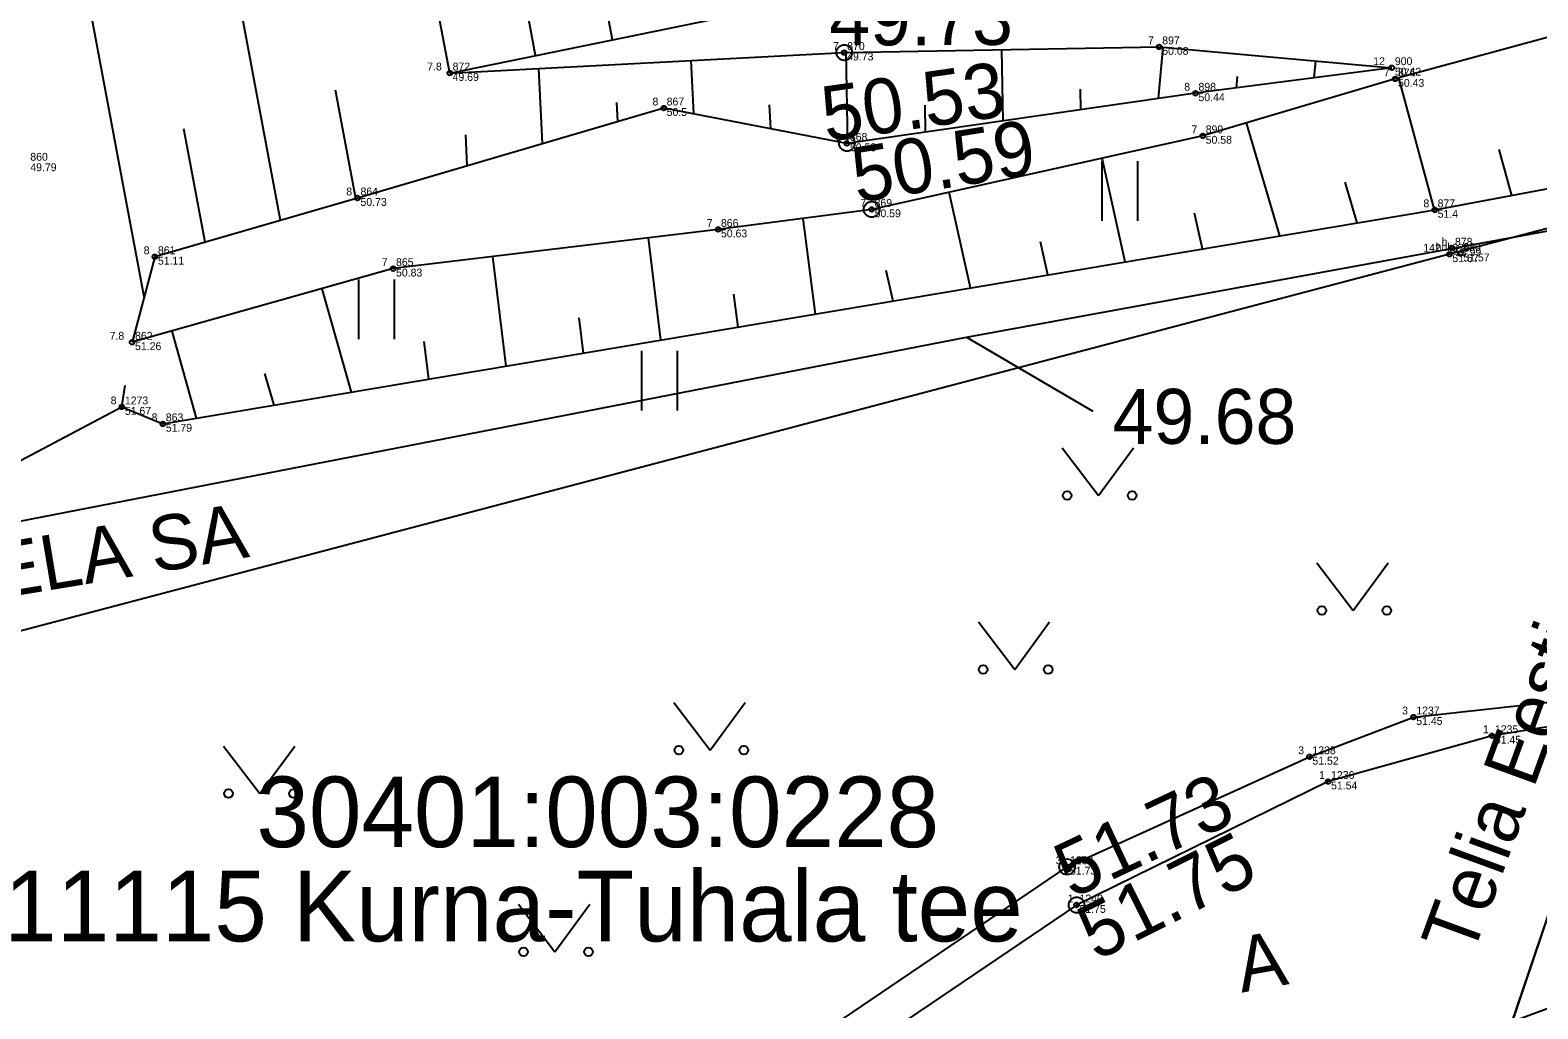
# Model space of a CAD drawing. Extents: x 543497 to 552146, y 6567125 to 6579845.
# Drawn here: x 546549.56 to 546568.77, y 6577762.04 to 6577774.51 of the extents above; entities that cross this region are included whole.
import ezdxf

# ---------------------------------------------------------------- set-up
doc = ezdxf.new("R2010")
doc.units = 0
for name, color, linetype in [('xref_Kangru tee 1_geodeesia$0$ABIJOONIS', 7, 'Continuous'), ('xref_Kangru tee 1_geodeesia$0$AED', 7, 'Continuous'), ('xref_Kangru tee 1_geodeesia$0$HALJASTUS', 7, 'Continuous'), ('xref_Kangru tee 1_geodeesia$0$korgus-EH2000', 7, 'Continuous'), ('xref_Kangru tee 1_geodeesia$0$mootkood', 7, 'Continuous'), ('xref_Kangru tee 1_geodeesia$0$MOOTKORG-eh2000', 7, 'Continuous'), ('xref_Kangru tee 1_geodeesia$0$mootmpunkt', 7, 'Continuous'), ('xref_Kangru tee 1_geodeesia$0$MOOTNR', 7, 'Continuous'), ('xref_Kangru tee 1_geodeesia$0$PIIR', 7, 'Continuous'), ('xref_Kangru tee 1_geodeesia$0$RELJEEF', 7, 'Continuous'), ('xref_Kangru tee 1_geodeesia$0$SITRASS', 7, 'Continuous'), ('xref_Kangru tee 1_geodeesia$0$TEE', 7, 'Continuous')]:
    doc.layers.add(name, color=color, linetype=linetype)

# ---------------------------------------------------------------- blocks, each defined once
blk = doc.blocks.new('xref_Kangru tee 1_geodeesia$0$MURU')
for p, q in [((-0.927, 1.213), (0, 0)), ((0, 0), (0.891, 1.213))]:
    blk.add_line(p, q)
for centre in [(-0.802, 0), (0.856, 0)]:
    blk.add_circle(centre, 0.11)
blk = doc.blocks.new('xref_Kangru tee 1_geodeesia$0$hein')
for p, q in [((-0.455, 0.761), (-0.455, -0.761)), ((0.455, 0.761), (0.455, -0.761))]:
    blk.add_line(p, q)

msp = doc.modelspace()

# ---------------------------------------------------------------- linework, layer by layer
at = {"layer": 'xref_Kangru tee 1_geodeesia$0$ABIJOONIS'}
msp.add_lwpolyline([(546561.492, 6577770.597), (546563.099, 6577769.653)], dxfattribs=at)
at = {"layer": 'xref_Kangru tee 1_geodeesia$0$AED'}
msp.add_lwpolyline([(546619.888, 6577778.288), (546609.506, 6577777.149), (546592.626, 6577775.302), (546575.912, 6577773.527), (546572.329, 6577772.88), (546567.646, 6577771.651), (546545.991, 6577765.945)], dxfattribs=at)
at = {"layer": 'xref_Kangru tee 1_geodeesia$0$korgus-EH2000'}
for centre in [(546559.933, 6577774.221), (546559.967, 6577773.064), (546560.282, 6577772.223), (546562.772, 6577763.848), (546562.894, 6577763.361)]:
    msp.add_circle(centre, 0.1, dxfattribs=at)
at = {"layer": 'xref_Kangru tee 1_geodeesia$0$mootmpunkt'}
for centre in [(546563.948, 6577774.293), (546559.933, 6577774.221), (546554.904, 6577773.96), (546566.913, 6577774.028), (546566.953, 6577773.885), (546564.41, 6577773.702), (546557.632, 6577773.514), (546564.502, 6577773.16), (546559.967, 6577773.064), (546553.73, 6577772.368), (546560.282, 6577772.223), (546567.458, 6577772.217), (546558.324, 6577771.967), (546551.148, 6577771.619), (546567.646, 6577771.651), (546567.679, 6577771.728), (546567.785, 6577771.661), (546554.183, 6577771.468), (546550.857, 6577770.53), (546550.727, 6577769.706), (546551.249, 6577769.491), (546567.186, 6577765.756), (546568.188, 6577765.517), (546565.862, 6577765.249), (546566.1, 6577764.934), (546562.772, 6577763.848), (546562.894, 6577763.361)]:
    msp.add_circle(centre, 0.03, dxfattribs=at)
at = {"layer": 'xref_Kangru tee 1_geodeesia$0$RELJEEF'}
for p, q in [((546555.998, 6577774.184), (546555.474, 6577776.98)), ((546552.749, 6577772.083), (546551.954, 6577776.32)), ((546551.012, 6577771.109), (546550.1, 6577775.972)), ((546556.977, 6577774.385), (546556.804, 6577775.311)), ((546554.904, 6577773.96), (546554.728, 6577774.898)), ((546558.016, 6577773.44), (546557.98, 6577774.12)), ((546559.98, 6577773.066), (546559.959, 6577774.221)), ((546561.959, 6577773.35), (546561.943, 6577774.257)), ((546563.939, 6577773.634), (546563.997, 6577774.289)), ((546565.921, 6577773.899), (546565.941, 6577774.115)), ((546556.088, 6577773.061), (546556.038, 6577774.019)), ((546564.93, 6577773.77), (546564.943, 6577773.914)), ((546553.709, 6577772.362), (546553.45, 6577773.742)), ((546562.949, 6577773.492), (546562.944, 6577773.753)), ((546567.457, 6577772.217), (546566.999, 6577773.898)), ((546557.047, 6577773.342), (546557.035, 6577773.585)), ((546558.998, 6577773.251), (546558.982, 6577773.557)), ((546560.969, 6577773.208), (546560.963, 6577773.552)), ((546551.788, 6577771.805), (546551.517, 6577773.249)), ((546555.128, 6577772.779), (546555.108, 6577773.175)), ((546565.485, 6577771.885), (546565.059, 6577773.325)), ((546568.44, 6577772.401), (546568.28, 6577772.987)), ((546563.512, 6577771.553), (546563.219, 6577772.875)), ((546566.471, 6577772.051), (546566.317, 6577772.569)), ((546561.54, 6577771.222), (546561.269, 6577772.442)), ((546564.498, 6577771.719), (546564.397, 6577772.177)), ((546559.568, 6577770.89), (546559.408, 6577772.109)), ((546557.595, 6577770.558), (546557.438, 6577771.86)), ((546562.526, 6577771.388), (546562.432, 6577771.811)), ((546555.623, 6577770.227), (546555.455, 6577771.621)), ((546560.554, 6577771.056), (546560.467, 6577771.446)), ((546553.651, 6577769.895), (546553.279, 6577771.213)), ((546558.581, 6577770.724), (546558.527, 6577771.143)), ((546556.609, 6577770.392), (546556.555, 6577770.842)), ((546551.678, 6577769.563), (546551.365, 6577770.673)), ((546554.637, 6577770.061), (546554.579, 6577770.541)), ((546552.665, 6577769.729), (546552.55, 6577770.134)), ((546550.727, 6577769.706), (546550.77, 6577769.981))]:
    msp.add_line(p, q, dxfattribs=at)
for points in [[(546554.904, 6577773.96), (546559.746, 6577774.952), (546563.529, 6577775.486), (546566.104, 6577776.076), (546569.451, 6577776.73), (546575.285, 6577777.669), (546591.928, 6577780.074), (546609.002, 6577782.024), (546618.326, 6577782.861), (546622.722, 6577782.991), (546628.579, 6577783.379), (546640.222, 6577783.284), (546642.311, 6577782.972), (546644.296, 6577782.453), (546645.105, 6577782.242), (546655.773, 6577781.108), (546661.524, 6577780.531), (546663.681, 6577779.627)], [(546663.681, 6577779.627), (546661.025, 6577779.482), (546655.667, 6577780.24), (546645.195, 6577781.158), (546642.472, 6577782.453), (546639.822, 6577782.844), (546628.438, 6577782.653), (546623.553, 6577781.976), (546622.345, 6577781.625), (546621.629, 6577780.852), (546620.046, 6577780.644), (546609.199, 6577780.378), (546592.284, 6577778.783), (546575.483, 6577776.209), (546566.953, 6577773.885), (546564.502, 6577773.16), (546560.282, 6577772.223), (546558.324, 6577771.967), (546554.183, 6577771.468), (546550.857, 6577770.53)], [(546550.727, 6577769.706), (546551.249, 6577769.491), (546567.458, 6577772.217), (546575.824, 6577773.787), (546592.716, 6577776.063), (546609.093, 6577777.913), (546620.403, 6577778.527), (546622.24, 6577778.664), (546623.137, 6577779.453), (546623.473, 6577780.609), (546628.431, 6577781.294), (546639.632, 6577780.958), (546641.087, 6577780.8), (546642.154, 6577779.459), (546644.484, 6577778.868), (546654.742, 6577777.987), (546663.525, 6577777.379)], [(546554.904, 6577773.96), (546559.933, 6577774.221), (546563.948, 6577774.293), (546566.913, 6577774.028)], [(546566.913, 6577774.028), (546564.41, 6577773.702), (546559.967, 6577773.064), (546557.632, 6577773.514), (546553.73, 6577772.368), (546551.148, 6577771.619), (546550.857, 6577770.53)], [(546540.89, 6577766.337), (546542.379, 6577767.142), (546548.926, 6577768.755), (546550.727, 6577769.706)]]:
    msp.add_lwpolyline(points, dxfattribs=at)
at = {"layer": 'xref_Kangru tee 1_geodeesia$0$SITRASS'}
msp.add_line((546567.217, 6577758.248), (546570.312, 6577767.388), dxfattribs=at)
for points in [[(546535.945, 6577765.191), (546545.774, 6577767.54), (546561.492, 6577770.597), (546573.177, 6577772.732), (546581.496, 6577773.983), (546601.337, 6577775.932), (546614.05, 6577777.466), (546620.283, 6577777.55), (546631.954, 6577777.234), (546639.759, 6577775.901), (546642.232, 6577774.863), (546647.939, 6577768.847), (546651.396, 6577764.746), (546652.558, 6577762.284)], [(546535.945, 6577765.191), (546545.774, 6577767.54), (546561.492, 6577770.597), (546573.177, 6577772.732), (546581.496, 6577773.983), (546601.337, 6577775.932), (546614.05, 6577777.466), (546620.283, 6577777.55), (546631.954, 6577777.234), (546639.759, 6577775.901)], [(546573.919, 6577773.607), (546572.16, 6577773.249), (546571.76, 6577771.98), (546570.312, 6577767.388), (546567.217, 6577758.248), (546566.268, 6577755.637), (546566.058, 6577755.169)]]:
    msp.add_lwpolyline(points, dxfattribs=at)
at = {"layer": 'xref_Kangru tee 1_geodeesia$0$TEE'}
for points in [[(546549.683, 6577756.576), (546553.201, 6577759.509), (546558.42, 6577760.898), (546562.772, 6577763.848), (546565.862, 6577765.249), (546567.186, 6577765.756), (546572.701, 6577766.362), (546573.338, 6577763.251), (546572.955, 6577762.223), (546569.286, 6577761.602), (546566.453, 6577760.312), (546564.257, 6577758.907), (546561.855, 6577757.167)], [(546561.477, 6577757.328), (546563.852, 6577759.682), (546565.891, 6577760.929), (546569.187, 6577762.154), (546572.715, 6577762.679), (546572.405, 6577764.522), (546572.025, 6577766.136), (546568.188, 6577765.517), (546566.1, 6577764.934), (546562.894, 6577763.361), (546558.715, 6577760.537), (546553.273, 6577758.859), (546549.683, 6577756.576), (546549.581, 6577755.854)]]:
    msp.add_lwpolyline(points, dxfattribs=at)

# ---------------------------------------------------------------- block references
at = {"layer": 'xref_Kangru tee 1_geodeesia$0$HALJASTUS', "xscale": 0.5, "yscale": 0.5}
for name, p in [('xref_Kangru tee 1_geodeesia$0$hein', (546563.443, 6577772.456)), ('xref_Kangru tee 1_geodeesia$0$hein', (546553.97, 6577770.951)), ('xref_Kangru tee 1_geodeesia$0$hein', (546557.577, 6577770.041)), ('xref_Kangru tee 1_geodeesia$0$MURU', (546563.174, 6577768.577)), ('xref_Kangru tee 1_geodeesia$0$MURU', (546566.42, 6577767.114)), ('xref_Kangru tee 1_geodeesia$0$MURU', (546562.105, 6577766.362)), ('xref_Kangru tee 1_geodeesia$0$MURU', (546558.225, 6577765.334)), ('xref_Kangru tee 1_geodeesia$0$MURU', (546552.485, 6577764.78)), ('xref_Kangru tee 1_geodeesia$0$MURU', (546556.246, 6577762.764))]:
    msp.add_blockref(name, p, dxfattribs=at)

# ---------------------------------------------------------------- texts
at = {"layer": 'xref_Kangru tee 1_geodeesia$0$ABIJOONIS'}
msp.add_text('49.68', height=0.7, dxfattribs=at).set_placement((546563.352, 6577769.236))
at = {"layer": 'xref_Kangru tee 1_geodeesia$0$korgus-EH2000'}
for s, rotation, p in [(' 49.73 ', 0.2292, (546559.481, 6577774.309)), (' 50.53 ', 8.1625, (546559.441, 6577773.048)), (' 50.59 ', 9.208, (546559.836, 6577772.266)), (' 51.73 ', 25.2072, (546562.598, 6577763.327)), (' 51.75 ', 26.6163, (546562.912, 6577762.526))]:
    msp.add_text(s, height=0.7, rotation=rotation, dxfattribs=at).set_placement(p)
at = {"layer": 'xref_Kangru tee 1_geodeesia$0$mootkood'}
for s, p in [(' 7', (546559.752, 6577774.254)), (' 7', (546563.767, 6577774.326)), (' 12', (546566.637, 6577774.061)), (' 7.8', (546554.58, 6577773.993)), (' 7', (546566.772, 6577773.918)), (' 8', (546564.229, 6577773.735)), (' 8', (546557.451, 6577773.547)), (' 8', (546559.786, 6577773.097)), (' 7', (546564.321, 6577773.193)), (' 8', (546553.549, 6577772.401)), (' 7', (546560.101, 6577772.256)), (' 8', (546567.277, 6577772.25)), (' 7', (546558.143, 6577772)), (' hhh', (546567.433, 6577771.694)), (' h', (546567.508, 6577771.761)), (' 8', (546550.967, 6577771.652)), (' 7', (546554.002, 6577771.501)), (' 142', (546567.275, 6577771.684)), (' 7.8', (546550.533, 6577770.563)), (' 8', (546550.546, 6577769.739)), (' 8', (546551.068, 6577769.524)), (' 3', (546567.005, 6577765.789)), (' 1', (546568.036, 6577765.55)), (' 3', (546565.681, 6577765.282)), (' 1', (546565.948, 6577764.967)), (' 3', (546562.591, 6577763.881)), (' 1', (546562.742, 6577763.394))]:
    msp.add_text(s, height=0.1, dxfattribs=at).set_placement(p)
at = {"layer": 'xref_Kangru tee 1_geodeesia$0$MOOTKORG-eh2000'}
for s, p in [(' 50.08', (546563.948, 6577774.193)), (' 49.73', (546559.933, 6577774.121)), (' 49.69', (546554.904, 6577773.86)), (' 50.42', (546566.913, 6577773.928)), (' 50.43', (546566.953, 6577773.785)), (' 50.44', (546564.41, 6577773.602)), (' 50.5', (546557.632, 6577773.414)), (' 50.58', (546564.502, 6577773.06)), (' 50.53', (546559.967, 6577772.964)), (' 49.79', (546549.522, 6577772.71)), (' 50.73', (546553.73, 6577772.268)), (' 50.59', (546560.282, 6577772.123)), (' 51.4', (546567.458, 6577772.117)), (' 50.63', (546558.324, 6577771.867)), (' 51.11', (546551.148, 6577771.519)), (' 51.67', (546567.646, 6577771.551)), (' 53.99', (546567.679, 6577771.628)), (' 51.57', (546567.785, 6577771.561)), (' 50.83', (546554.183, 6577771.368)), (' 51.26', (546550.857, 6577770.43)), (' 51.67', (546550.727, 6577769.606)), (' 51.79', (546551.249, 6577769.391)), (' 51.45', (546567.186, 6577765.656)), (' 51.45', (546568.188, 6577765.417)), (' 51.52', (546565.862, 6577765.149)), (' 51.54', (546566.1, 6577764.834)), (' 51.73', (546562.772, 6577763.748)), (' 51.75', (546562.894, 6577763.261))]:
    msp.add_text(s, height=0.1, dxfattribs=at).set_placement(p)
at = {"layer": 'xref_Kangru tee 1_geodeesia$0$MOOTNR'}
for s, p in [(' 870', (546559.933, 6577774.254)), (' 897', (546563.948, 6577774.326)), (' 900', (546566.913, 6577774.061)), (' 872', (546554.904, 6577773.993)), (' 876', (546566.953, 6577773.918)), (' 898', (546564.41, 6577773.735)), (' 867', (546557.632, 6577773.547)), (' 868', (546559.967, 6577773.097)), (' 899', (546564.502, 6577773.193)), (' 860', (546549.522, 6577772.843)), (' 864', (546553.73, 6577772.401)), (' 869', (546560.282, 6577772.256)), (' 877', (546567.458, 6577772.25)), (' 866', (546558.324, 6577772)), (' 878', (546567.679, 6577771.761)), (' 880', (546567.785, 6577771.694)), (' 861', (546551.148, 6577771.652)), (' 865', (546554.183, 6577771.501)), (' 879', (546567.646, 6577771.684)), (' 862', (546550.857, 6577770.563)), (' 1273', (546550.727, 6577769.739)), (' 863', (546551.249, 6577769.524)), (' 1237', (546567.186, 6577765.789)), (' 1235', (546568.188, 6577765.55)), (' 1238', (546565.862, 6577765.282)), (' 1236', (546566.1, 6577764.967)), (' 1239', (546562.772, 6577763.881)), (' 1240', (546562.894, 6577763.394))]:
    msp.add_text(s, height=0.1, dxfattribs=at).set_placement(p)
at = {"layer": 'xref_Kangru tee 1_geodeesia$0$PIIR'}
for s, p in [('30401:003:0228', (546552.441, 6577764.098)), ('11115 Kurna-Tuhala tee', (546549.227, 6577762.898))]:
    msp.add_text(s, height=0.9, dxfattribs=at).set_placement(p)
at = {"layer": 'xref_Kangru tee 1_geodeesia$0$SITRASS'}
for s, rotation, p in [('ELA SA', 9.4435, (546549.132, 6577767.259)), ('Telia Eesti AS', 69.9337, (546567.932, 6577762.684))]:
    msp.add_text(s, height=0.7, rotation=rotation, dxfattribs=at).set_placement(p)
at = {"layer": 'xref_Kangru tee 1_geodeesia$0$TEE'}
msp.add_text('A', height=0.7, rotation=10.1972, dxfattribs=at).set_placement((546564.997, 6577762.244))

doc.saveas('drawing.dxf')
